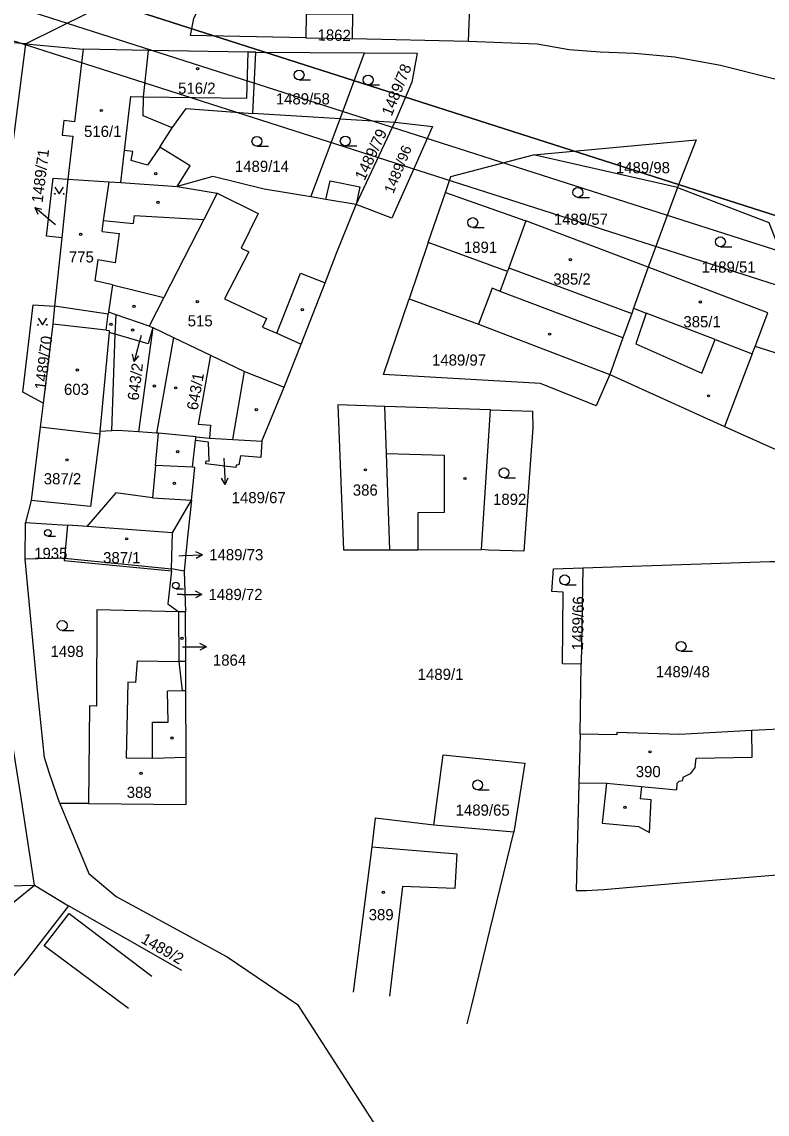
# Model space of a CAD drawing. Extents: x -779330 to -774454, y -1144748 to -1142831.
# Drawn here: x -777487.4 to -777374.1, y -1144015.8 to -1143849.7 of the extents above; entities that cross this region are included whole.
import ezdxf

# ---------------------------------------------------------------- set-up
doc = ezdxf.new("R2010")
doc.units = 0
for name, color, linetype in [('Hranice parcel', 7, 'Continuous'), ('Parcelní čísla', 7, 'Continuous'), ('Pop  PČ popisy', 7, 'Continuous'), ('Vnitřní kresba', 7, 'Continuous'), ('Vrstva 1', 7, 'Continuous'), ('Značky budov', 7, 'Continuous'), ('Značky kultur', 7, 'Continuous')]:
    doc.layers.add(name, color=color, linetype=linetype)

msp = doc.modelspace()

# ---------------------------------------------------------------- linework, layer by layer
at = {"layer": 'Hranice parcel'}
for p, q in [((-777418.55, -1143826.88), (-777419.52, -1143852.7)), ((-777449.55, -1143834.59), (-777486.78, -1143853.07)), ((-777486.78, -1143853.07), (-777496.53, -1143852.24)), ((-777419.52, -1143852.7), (-777437.09, -1143852.27)), ((-777489.3, -1143872.89), (-777486.78, -1143853.07)), ((-777486.78, -1143853.07), (-777478.06, -1143853.89)), ((-777468.1, -1143854.06), (-777478.06, -1143853.89)), ((-777452.27, -1143863.63), (-777451.81, -1143854.32)), ((-777451.81, -1143854.32), (-777435.27, -1143854.43)), ((-777439.01, -1143864.45), (-777435.27, -1143854.43)), ((-777439.01, -1143864.45), (-777452.27, -1143863.63)), ((-777443.44, -1143876.33), (-777439.01, -1143864.45)), ((-777439.01, -1143864.45), (-777430.65, -1143864.96)), ((-777436.54, -1143877.5), (-777430.65, -1143864.96)), ((-777430.65, -1143864.96), (-777424.95, -1143865.64)), ((-777387.71, -1143874.9), (-777409.57, -1143869.91)), ((-777480.4, -1143873.62), (-777481.32, -1143882.55)), ((-777480.4, -1143873.62), (-777474.11, -1143874.04)), ((-777387.71, -1143874.9), (-777392.16, -1143887)), ((-777425.6, -1143883.24), (-777422.97, -1143875.68)), ((-777422.97, -1143875.68), (-777410.76, -1143879.95)), ((-777431.12, -1143879.55), (-777436.54, -1143877.5)), ((-777392.16, -1143887), (-777410.76, -1143879.95)), ((-777481.32, -1143882.55), (-777482.42, -1143892.94)), ((-777425.6, -1143883.24), (-777428.52, -1143891.82)), ((-777432.39, -1143903.31), (-777428.52, -1143891.82)), ((-777473.06, -1143894.25), (-777474.19, -1143893.86)), ((-777468.03, -1143895.99), (-777473.06, -1143894.25)), ((-777464.32, -1143897.7), (-777466.91, -1143912.26)), ((-777397.97, -1143903.33), (-777400.06, -1143908.12)), ((-777450.9, -1143913.45), (-777447.5, -1143905.28)), ((-777484.13, -1143907.67), (-777484.58, -1143911.35)), ((-777417.51, -1143929.96), (-777416.15, -1143908.69)), ((-777461.42, -1143917.43), (-777460.96, -1143913.39)), ((-777460.96, -1143913.39), (-777460.89, -1143912.79)), ((-777464.49, -1143927.39), (-777461.56, -1143922.46)), ((-777486.85, -1143931.42), (-777486.83, -1143925.84)), ((-777486.83, -1143925.84), (-777480.42, -1143926.26)), ((-777480.42, -1143926.26), (-777480.9, -1143931.26)), ((-777464.62, -1143932.88), (-777464.49, -1143927.39)), ((-777480.9, -1143931.26), (-777486.85, -1143931.42)), ((-777464.65, -1143933.18), (-777464.62, -1143932.88)), ((-777462.69, -1143933.25), (-777464.62, -1143932.88)), ((-777462.69, -1143933.25), (-777462.49, -1143939.42)), ((-777402.11, -1143932.75), (-777402.33, -1143947.36)), ((-777462.49, -1143939.42), (-777463.49, -1143939.4)), ((-777402.5, -1143958.01), (-777402.33, -1143947.36)), ((-777462.43, -1143951.45), (-777462.93, -1143951.45)), ((-777477.24, -1143968.59), (-777481.58, -1143968.55)), ((-777412.57, -1143972.94), (-777424.73, -1143971.85)), ((-777497.98, -1143981.37), (-777485.45, -1143980.98)), ((-777485.45, -1143980.98), (-777480.26, -1143984.1)), ((-777463.05, -1143993.95), (-777480.26, -1143984.1))]:
    msp.add_line(p, q, dxfattribs=at)
for points in [[(-777444.18, -1143852.13), (-777461.74, -1143851.77), (-777461.25, -1143849.21), (-777460.37, -1143847.4), (-777458.98, -1143845.51), (-777456.06, -1143841.9), (-777449.55, -1143834.59)], [(-777437.09, -1143852.27), (-777437.07, -1143848.56), (-777444.17, -1143848.54), (-777444.18, -1143852.13)], [(-777444.18, -1143852.13), (-777437.61, -1143852.26), (-777437.09, -1143852.27)], [(-777478.06, -1143853.89), (-777479.37, -1143864.92), (-777480.99, -1143864.73), (-777481.26, -1143866.92), (-777479.63, -1143867.11), (-777480.4, -1143873.62)], [(-777327.16, -1143876.09), (-777335.43, -1143873.14), (-777361.49, -1143861.7), (-777365.24, -1143860.37), (-777381.18, -1143856.34), (-777388.13, -1143855.07), (-777394.23, -1143854.52), (-777399.48, -1143854.32), (-777404.16, -1143853.96), (-777409.04, -1143853.1), (-777419.52, -1143852.7)], [(-777464.54, -1143865.84), (-777468.91, -1143864), (-777468.86, -1143861.1), (-777468.1, -1143854.06)], [(-777451.81, -1143854.32), (-777452.98, -1143854.31), (-777468.1, -1143854.06)], [(-777435.27, -1143854.43), (-777427.29, -1143854.49), (-777428.1, -1143858.9), (-777430.65, -1143864.96)], [(-777464.54, -1143865.84), (-777462.38, -1143862.89), (-777452.27, -1143863.63)], [(-777463.76, -1143874.74), (-777461.79, -1143871.61), (-777466.4, -1143868.75), (-777464.54, -1143865.84)], [(-777424.95, -1143865.64), (-777427.63, -1143871.69), (-777431.12, -1143879.55)], [(-777409.57, -1143869.91), (-777384.85, -1143867.66), (-777387.71, -1143874.9)], [(-777422.97, -1143875.68), (-777422.14, -1143873.24), (-777409.57, -1143869.91)], [(-777481.32, -1143882.55), (-777483.64, -1143882.28), (-777482.59, -1143873.48), (-777480.4, -1143873.62)], [(-777443.44, -1143876.33), (-777450.52, -1143875.13), (-777458.32, -1143873.25), (-777463.76, -1143874.74)], [(-777474.11, -1143874.04), (-777472.34, -1143874.16), (-777463.76, -1143874.74)], [(-777463.76, -1143874.74), (-777457.68, -1143875.75), (-777459.73, -1143879.75), (-777465.81, -1143891.65), (-777468.03, -1143895.99)], [(-777387.71, -1143874.9), (-777373.82, -1143880.22), (-777368.59, -1143893.6), (-777368.48, -1143895.35), (-777368.62, -1143898.23), (-777369.33, -1143901.14)], [(-777436.54, -1143877.5), (-777441.17, -1143876.72), (-777443.44, -1143876.33)], [(-777447.5, -1143905.28), (-777444.89, -1143898.71), (-777441.28, -1143889.42), (-777439.52, -1143884.86), (-777436.54, -1143877.5)], [(-777410.76, -1143879.95), (-777413.35, -1143887.12), (-777413.56, -1143887.69), (-777425.6, -1143883.24)], [(-777392.16, -1143887), (-777394.39, -1143893.25), (-777394.67, -1143894.05), (-777395.99, -1143897.77), (-777397.97, -1143903.33)], [(-777369.33, -1143901.14), (-777375.91, -1143899.08), (-777373.97, -1143893.98), (-777392.16, -1143887)], [(-777428.52, -1143891.82), (-777417.94, -1143895.67), (-777397.97, -1143903.33)], [(-777484.13, -1143907.67), (-777487.22, -1143906.02), (-777485.63, -1143892.74), (-777482.42, -1143892.94)], [(-777482.42, -1143892.94), (-777482.69, -1143895.68), (-777484.13, -1143907.67)], [(-777474.19, -1143893.86), (-777474.23, -1143894.15), (-777482.42, -1143892.94)], [(-777473.7, -1143911.9), (-777473.17, -1143897.22), (-777473.06, -1143894.25)], [(-777468.03, -1143895.99), (-777467.45, -1143896.19), (-777464.32, -1143897.7)], [(-777464.32, -1143897.7), (-777458.69, -1143900.41), (-777453.51, -1143902.88), (-777447.5, -1143905.28)], [(-777397.97, -1143903.33), (-777380.56, -1143911.25), (-777372.76, -1143914.75), (-777369.33, -1143901.14)], [(-777400.06, -1143908.12), (-777408.55, -1143904.69), (-777432.39, -1143903.31)], [(-777416.15, -1143908.69), (-777432.2, -1143908.19), (-777439.33, -1143907.97), (-777438.5, -1143930.01), (-777431.41, -1143930), (-777427.19, -1143929.98), (-777417.51, -1143929.96)], [(-777416.15, -1143908.69), (-777409.77, -1143908.89), (-777409.7, -1143911.46), (-777411.07, -1143930.18), (-777416.41, -1143930.04), (-777417.51, -1143929.96)], [(-777484.58, -1143911.35), (-777485.95, -1143922.48), (-777486.83, -1143925.84)], [(-777473.7, -1143911.9), (-777475.5, -1143911.99), (-777475.53, -1143912.39), (-777484.58, -1143911.35)], [(-777466.91, -1143912.26), (-777469.63, -1143912.07), (-777472.78, -1143911.85), (-777473.7, -1143911.9)], [(-777460.89, -1143912.79), (-777466.62, -1143912.28), (-777466.91, -1143912.26)], [(-777450.9, -1143913.45), (-777451.05, -1143915.97), (-777454.15, -1143915.69), (-777454.41, -1143917.08), (-777454.78, -1143917.12), (-777454.87, -1143917.46), (-777459.42, -1143916.92), (-777459.36, -1143916.44), (-777458.92, -1143916.5), (-777458.98, -1143913.64), (-777460.96, -1143913.39)], [(-777460.89, -1143912.79), (-777458.86, -1143913.02), (-777455.28, -1143913.2), (-777450.9, -1143913.45)], [(-777461.42, -1143917.43), (-777467.05, -1143917.15), (-777467.49, -1143922.1), (-777473.07, -1143921.35), (-777477.48, -1143926.47), (-777478.08, -1143926.42), (-777480.42, -1143926.26)], [(-777461.56, -1143922.46), (-777461.07, -1143917.46), (-777461.42, -1143917.43)], [(-777461.56, -1143922.46), (-777462.24, -1143928.53), (-777462.69, -1143933.25)], [(-777481.58, -1143968.55), (-777483.22, -1143963.84), (-777483.95, -1143961.55), (-777484.96, -1143951.84), (-777486.85, -1143931.42)], [(-777480.9, -1143931.26), (-777480.96, -1143931.61), (-777464.65, -1143933.18)], [(-777402.11, -1143932.75), (-777373.6, -1143931.76), (-777372.2, -1143931.77)], [(-777464.65, -1143933.18), (-777465.2, -1143938.21), (-777463.49, -1143939.4)], [(-777402.33, -1143947.36), (-777405.2, -1143947.32), (-777405.06, -1143936.43), (-777406.8, -1143936.33), (-777406.57, -1143932.89), (-777402.11, -1143932.75)], [(-777463.49, -1143939.4), (-777476, -1143939.12), (-777476.05, -1143953.74), (-777477.1, -1143953.73), (-777477.24, -1143968.59)], [(-777462.93, -1143951.45), (-777463.45, -1143946.96), (-777463.49, -1143939.4)], [(-777462.43, -1143951.45), (-777462.45, -1143946.98), (-777462.49, -1143939.42)], [(-777477.24, -1143968.59), (-777462.41, -1143968.73), (-777462.41, -1143961.51), (-777462.43, -1143951.45)], [(-777485.45, -1143980.98), (-777487.53, -1143967.33), (-777488.73, -1143959.74), (-777489.74, -1143953.34)], [(-777402.5, -1143958.01), (-777402.7, -1143965.53), (-777403.13, -1143981.77), (-777401.59, -1143981.77), (-777398.88, -1143981.65), (-777389.09, -1143980.8), (-777372.01, -1143979.38)], [(-777372.24, -1143957.25), (-777376.4, -1143957.46), (-777387.4, -1143958.06), (-777396.94, -1143957.77), (-777396.94, -1143958.12), (-777402.5, -1143958.01)], [(-777424.73, -1143971.85), (-777423.31, -1143961.18), (-777410.93, -1143962.41), (-777412.57, -1143972.94)], [(-777481.58, -1143968.55), (-777477.17, -1143979.2), (-777473.05, -1143982.72), (-777456.14, -1143991.88), (-777445.46, -1143999.14), (-777423.92, -1144032.56), (-777417.93, -1144044.16), (-777413.32, -1144046.11), (-777406.13, -1144045.3), (-777379.07, -1144045.85)], [(-777424.73, -1143971.85), (-777433.65, -1143970.77), (-777434.18, -1143975.17), (-777436.99, -1143997.24)], [(-777419.7, -1144002.05), (-777418.99, -1143999.25), (-777416.17, -1143987.69), (-777412.57, -1143972.94)], [(-777495.24, -1143987.67), (-777494.46, -1143988.3), (-777485.45, -1143980.98)], [(-777480.26, -1143984.1), (-777486.85, -1143992.66), (-777490.53, -1143997.04), (-777494.49, -1144001.76)]]:
    msp.add_lwpolyline(points, dxfattribs=at)
at = {"layer": 'Pop  PČ popisy'}
for p, q in [((-777483.11, -1143879.85), (-777485.41, -1143877.92)), ((-777485.41, -1143877.92), (-777484.32, -1143878.18)), ((-777485.41, -1143877.92), (-777484.96, -1143878.95)), ((-777482.25, -1143880.58), (-777483.11, -1143879.85)), ((-777469.54, -1143898.45), (-777470.32, -1143901.35)), ((-777469.25, -1143897.39), (-777469.54, -1143898.45)), ((-777470.32, -1143901.35), (-777470.54, -1143900.25)), ((-777470.32, -1143901.35), (-777469.57, -1143900.51)), ((-777456.68, -1143916.08), (-777456.63, -1143917.07)), ((-777456.63, -1143917.07), (-777456.47, -1143920.07)), ((-777456.47, -1143920.07), (-777457.03, -1143919.09)), ((-777456.47, -1143920.07), (-777456.03, -1143919.04)), ((-777459.89, -1143930.76), (-777460.91, -1143930.29)), ((-777463.52, -1143930.89), (-777462.89, -1143930.86)), ((-777462.89, -1143930.86), (-777459.89, -1143930.76)), ((-777459.89, -1143930.76), (-777460.87, -1143931.29)), ((-777463, -1143936.78), (-777463.76, -1143936.78)), ((-777463, -1143936.78), (-777460, -1143936.78)), ((-777460, -1143936.78), (-777461, -1143936.28)), ((-777460, -1143936.78), (-777461, -1143937.28)), ((-777462.95, -1143944.75), (-777462.33, -1143944.76)), ((-777462.33, -1143944.76), (-777459.33, -1143944.76)), ((-777459.33, -1143944.76), (-777460.33, -1143944.26)), ((-777459.33, -1143944.76), (-777460.33, -1143945.26))]:
    msp.add_line(p, q, dxfattribs=at)
at = {"layer": 'Vnitřní kresba'}
for p, q in [((-777453.19, -1143861.34), (-777452.98, -1143854.31)), ((-777471.77, -1143869.29), (-777470.8, -1143861.07)), ((-777470.8, -1143861.07), (-777468.86, -1143861.1)), ((-777468.86, -1143861.1), (-777453.19, -1143861.34)), ((-777466.4, -1143868.75), (-777468.27, -1143871.5)), ((-777472.34, -1143874.16), (-777471.77, -1143869.29)), ((-777470.49, -1143869.44), (-777471.77, -1143869.29)), ((-777470.75, -1143870.78), (-777470.49, -1143869.44)), ((-777468.27, -1143871.5), (-777470.75, -1143870.78)), ((-777441.17, -1143876.72), (-777440.49, -1143873.91)), ((-777440.49, -1143873.91), (-777435.97, -1143874.82)), ((-777474.95, -1143879.92), (-777474.11, -1143874.04)), ((-777435.97, -1143874.82), (-777436.54, -1143877.5)), ((-777457.68, -1143875.75), (-777451.44, -1143878.84)), ((-777451.44, -1143878.84), (-777454.05, -1143884.11)), ((-777475.19, -1143881.59), (-777474.95, -1143879.92)), ((-777474.95, -1143879.92), (-777470.38, -1143880.35)), ((-777470.38, -1143880.35), (-777470.27, -1143879.16)), ((-777470.27, -1143879.16), (-777459.73, -1143879.75)), ((-777475.19, -1143881.59), (-777472.57, -1143881.89)), ((-777472.57, -1143881.89), (-777473.18, -1143886.37)), ((-777452.89, -1143884.68), (-777456.57, -1143891.83)), ((-777454.05, -1143884.11), (-777452.89, -1143884.68)), ((-777475.81, -1143885.92), (-777476.26, -1143889.07)), ((-777473.18, -1143886.37), (-777475.81, -1143885.92)), ((-777413.35, -1143887.12), (-777394.67, -1143894.05)), ((-777448.63, -1143897.05), (-777445.03, -1143887.92)), ((-777445.03, -1143887.92), (-777441.28, -1143889.42)), ((-777414.64, -1143890.69), (-777413.56, -1143887.69)), ((-777473.61, -1143889.72), (-777476.26, -1143889.07)), ((-777473.61, -1143889.72), (-777474.19, -1143893.86)), ((-777473.61, -1143889.72), (-777465.81, -1143891.65)), ((-777415.88, -1143890.22), (-777417.94, -1143895.67)), ((-777414.64, -1143890.69), (-777415.88, -1143890.22)), ((-777456.57, -1143891.83), (-777450.18, -1143894.8)), ((-777395.99, -1143897.77), (-777414.64, -1143890.69)), ((-777394.39, -1143893.25), (-777392.46, -1143893.99)), ((-777474.57, -1143896.59), (-777474.23, -1143894.15)), ((-777450.18, -1143894.8), (-777450.8, -1143896.14)), ((-777392.46, -1143893.99), (-777394.03, -1143898.65)), ((-777381.99, -1143898.03), (-777392.46, -1143893.99)), ((-777474.57, -1143896.59), (-777482.69, -1143895.68)), ((-777474.11, -1143896.95), (-777475.5, -1143911.99)), ((-777474.57, -1143896.59), (-777474.08, -1143896.65)), ((-777474.08, -1143896.65), (-777474.11, -1143896.95)), ((-777473.17, -1143897.22), (-777474.11, -1143896.95)), ((-777467.45, -1143896.19), (-777469.63, -1143912.07)), ((-777467.45, -1143896.19), (-777468.18, -1143898.68)), ((-777450.8, -1143896.14), (-777448.63, -1143897.05)), ((-777448.63, -1143897.05), (-777444.89, -1143898.71)), ((-777468.18, -1143898.68), (-777473.17, -1143897.22)), ((-777394.03, -1143898.65), (-777383.98, -1143903.14)), ((-777383.98, -1143903.14), (-777381.99, -1143898.03)), ((-777381.99, -1143898.03), (-777376.34, -1143900.2)), ((-777458.69, -1143900.41), (-777460.58, -1143910.9)), ((-777376.34, -1143900.2), (-777380.56, -1143911.25)), ((-777376.34, -1143900.2), (-777375.91, -1143899.08)), ((-777455.28, -1143913.2), (-777453.51, -1143902.88)), ((-777431.94, -1143915.36), (-777432.2, -1143908.19)), ((-777460.58, -1143910.9), (-777458.72, -1143911.03)), ((-777458.72, -1143911.03), (-777458.86, -1143913.02)), ((-777475.53, -1143912.39), (-777476.96, -1143923.4)), ((-777467.05, -1143917.15), (-777466.62, -1143912.28)), ((-777431.41, -1143930), (-777431.94, -1143915.36)), ((-777431.94, -1143915.36), (-777423.2, -1143915.61)), ((-777423.2, -1143915.61), (-777423.18, -1143924.34)), ((-777476.96, -1143923.4), (-777485.95, -1143922.48)), ((-777467.49, -1143922.1), (-777461.56, -1143922.46)), ((-777423.18, -1143924.34), (-777427.2, -1143924.35)), ((-777427.2, -1143924.35), (-777427.19, -1143929.98)), ((-777464.49, -1143927.39), (-777477.48, -1143926.47)), ((-777480.9, -1143931.26), (-777464.62, -1143932.88)), ((-777469.85, -1143946.85), (-777470.1, -1143950.16)), ((-777469.85, -1143946.85), (-777463.45, -1143946.96)), ((-777462.45, -1143946.98), (-777463.45, -1143946.96)), ((-777471.27, -1143950.14), (-777471.5, -1143961.64)), ((-777470.1, -1143950.16), (-777471.27, -1143950.14)), ((-777462.93, -1143951.45), (-777465.23, -1143951.47)), ((-777465.13, -1143956.19), (-777465.23, -1143951.47)), ((-777467.51, -1143956.2), (-777465.13, -1143956.19)), ((-777467.5, -1143961.67), (-777467.51, -1143956.2)), ((-777376.35, -1143961.5), (-777376.4, -1143957.46)), ((-777471.5, -1143961.64), (-777467.5, -1143961.67)), ((-777467.5, -1143961.67), (-777462.41, -1143961.51)), ((-777385.03, -1143963.06), (-777384.86, -1143961.67)), ((-777384.86, -1143961.67), (-777376.35, -1143961.5)), ((-777385.03, -1143963.06), (-777385.78, -1143964.07)), ((-777387.78, -1143965.53), (-777387.43, -1143965.19)), ((-777387.43, -1143965.19), (-777386.96, -1143965.08)), ((-777386.91, -1143964.61), (-777386.96, -1143965.08)), ((-777385.78, -1143964.07), (-777386.91, -1143964.61)), ((-777398.52, -1143965.48), (-777402.7, -1143965.53)), ((-777398.52, -1143965.48), (-777399.16, -1143971.54)), ((-777398.52, -1143965.48), (-777393.19, -1143965.98)), ((-777393.19, -1143965.98), (-777393.36, -1143967.87)), ((-777393.19, -1143965.98), (-777387.87, -1143966.47)), ((-777387.78, -1143965.53), (-777387.87, -1143966.47)), ((-777391.7, -1143968.02), (-777393.36, -1143967.87)), ((-777391.97, -1143972.95), (-777391.7, -1143968.02)), ((-777399.16, -1143971.54), (-777393.63, -1143972.04)), ((-777393.63, -1143972.04), (-777391.97, -1143972.95)), ((-777434.18, -1143975.17), (-777421.25, -1143976.21)), ((-777421.25, -1143976.21), (-777421.57, -1143981.47)), ((-777429.52, -1143981.19), (-777431.51, -1143997.85)), ((-777421.57, -1143981.47), (-777429.52, -1143981.19)), ((-777483.96, -1143990.21), (-777480.16, -1143985.27)), ((-777480.16, -1143985.27), (-777467.6, -1143994.84)), ((-777471.17, -1143999.75), (-777483.96, -1143990.21))]:
    msp.add_line(p, q, dxfattribs=at)
at = {"layer": 'Vrstva 1'}
for points in [[(-776606.88, -1143822.95), (-777806.9, -1143438.86), (-777897.43, -1143721.71), (-776697.42, -1144105.81)], [(-776700.65, -1144099.52), (-777891.15, -1143718.47), (-777803.66, -1143445.14), (-776613.17, -1143826.19)], [(-776619.45, -1143829.42), (-777605.19, -1143513.91), (-777689.63, -1143777.73), (-776703.89, -1144093.24)], [(-776703.89, -1144093.24), (-777689.63, -1143777.73), (-777605.19, -1143513.91), (-776619.45, -1143829.42)]]:
    msp.add_lwpolyline(points, close=True, dxfattribs=at)
at = {"layer": 'Značky budov'}
for centre in [(-777460.65, -1143856.82), (-777475.3, -1143863.19), (-777467.02, -1143872.79), (-777466.68, -1143877.14), (-777478.44, -1143882), (-777403.98, -1143885.89), (-777460.7, -1143892.28), (-777384.21, -1143892.3), (-777470.31, -1143892.99), (-777444.75, -1143893.48), (-777473.84, -1143895.72), (-777470.55, -1143896.59), (-777407.15, -1143897.2), (-777478.96, -1143902.65), (-777467.23, -1143905.07), (-777464.01, -1143905.36), (-777382.99, -1143906.58), (-777451.75, -1143908.67), (-777463.68, -1143915.05), (-777480.52, -1143916.31), (-777435.15, -1143917.83), (-777464.19, -1143919.89), (-777420.01, -1143919.15), (-777471.45, -1143928.32), (-777463.02, -1143943.43), (-777464.54, -1143958.62), (-777391.87, -1143960.71), (-777469.26, -1143963.97), (-777395.69, -1143969.13), (-777432.41, -1143982.06)]:
    msp.add_circle(centre, 0.175, dxfattribs=at)
at = {"layer": 'Značky kultur'}
for p, q in [((-777445.23, -1143858.54), (-777443.48, -1143858.54)), ((-777434.73, -1143859.3), (-777432.98, -1143859.3)), ((-777451.64, -1143868.64), (-777449.89, -1143868.64)), ((-777438.21, -1143868.58), (-777436.46, -1143868.58)), ((-777402.85, -1143876.4), (-777401.1, -1143876.4)), ((-777418.83, -1143880.98), (-777417.08, -1143880.98)), ((-777381.18, -1143883.91), (-777379.43, -1143883.91)), ((-777414.07, -1143919.04), (-777412.32, -1143919.04)), ((-777483.44, -1143927.91), (-777482.26, -1143927.91)), ((-777404.85, -1143935.31), (-777403.1, -1143935.31)), ((-777463.97, -1143935.9), (-777462.8, -1143935.9)), ((-777481.24, -1143942.25), (-777479.49, -1143942.25)), ((-777387.16, -1143945.42), (-777385.41, -1143945.42)), ((-777418.08, -1143966.49), (-777416.33, -1143966.49))]:
    msp.add_line(p, q, dxfattribs=at)
for points in [[(-777482.36, -1143874.86), (-777481.69, -1143875.87), (-777481.02, -1143874.86)], [(-777484.92, -1143894.77), (-777484.25, -1143895.78), (-777483.58, -1143894.77)]]:
    msp.add_lwpolyline(points, dxfattribs=at)
for centre, radius in [((-777445.23, -1143857.79), 0.75), ((-777434.73, -1143858.55), 0.75), ((-777451.64, -1143867.89), 0.75), ((-777438.21, -1143867.83), 0.75), ((-777402.85, -1143875.65), 0.75), ((-777482.36, -1143875.87), 0.067), ((-777481.02, -1143875.87), 0.067), ((-777418.83, -1143880.23), 0.75), ((-777381.18, -1143883.16), 0.75), ((-777484.92, -1143895.78), 0.067), ((-777483.58, -1143895.78), 0.067), ((-777414.07, -1143918.29), 0.75), ((-777483.44, -1143927.41), 0.502), ((-777463.98, -1143935.4), 0.502), ((-777404.85, -1143934.56), 0.75), ((-777481.24, -1143941.5), 0.75), ((-777387.16, -1143944.67), 0.75), ((-777418.08, -1143965.74), 0.75)]:
    msp.add_circle(centre, radius, dxfattribs=at)

# ---------------------------------------------------------------- texts
at = {"layer": 'Parcelní čísla'}
for s, height, rotation, p in [('1862', 1.7, 359, (-777442.44, -1143852.54)), ('1489/78', 1.7, 68, (-777431.16, -1143864.16)), ('1489/79', 1.7, 65, (-777435.28, -1143873.96)), ('1489/96', 1.568, 68, (-777430.9, -1143875.93)), ('1489/71', 1.7, 83, (-777484.22, -1143877.29)), ('1489/70', 1.7, 83, (-777483.75, -1143905.74)), ('643/2', 1.7, 83, (-777469.64, -1143907.35)), ('643/1', 1.7, 80, (-777460.66, -1143908.84)), ('1489/66', 1.7, 89, (-777402.06, -1143945.29)), ('1489/2', 1.7, 330, (-777469.42, -1143989.63))]:
    msp.add_text(s, height=height, rotation=rotation, dxfattribs=at).set_placement(p)
for s, p in [('516/2', (-777463.62, -1143860.65)), ('1489/58', (-777448.77, -1143862.27)), ('516/1', (-777477.92, -1143867.22)), ('1489/14', (-777454.99, -1143872.53)), ('1489/98', (-777397.07, -1143872.73)), ('1489/57', (-777406.5, -1143880.57)), ('1891', (-777420.18, -1143884.84)), ('775', (-777480.22, -1143886.3)), ('1489/51', (-777384.04, -1143887.85)), ('385/2', (-777406.58, -1143889.67)), ('515', (-777462.16, -1143896.02)), ('385/1', (-777386.81, -1143896.16)), ('1489/97', (-777425.02, -1143901.99)), ('603', (-777480.97, -1143906.44)), ('387/2', (-777484.04, -1143920.04)), ('386', (-777437.06, -1143921.75)), ('1489/67', (-777455.48, -1143922.9)), ('1892', (-777415.74, -1143923.16)), ('1935', (-777485.5, -1143931.39)), ('387/1', (-777475.02, -1143932.04)), ('1489/73', (-777458.89, -1143931.59)), ('1489/72', (-777459, -1143937.63)), ('1498', (-777483.03, -1143946.29)), ('1864', (-777458.33, -1143947.61)), ('1489/1', (-777427.2, -1143949.77)), ('1489/48', (-777391, -1143949.38)), ('390', (-777394.05, -1143964.56)), ('388', (-777471.43, -1143967.72)), ('1489/65', (-777421.43, -1143970.42)), ('389', (-777434.65, -1143986.32))]:
    msp.add_text(s, height=1.7, dxfattribs=at).set_placement(p)

doc.saveas('drawing.dxf')
